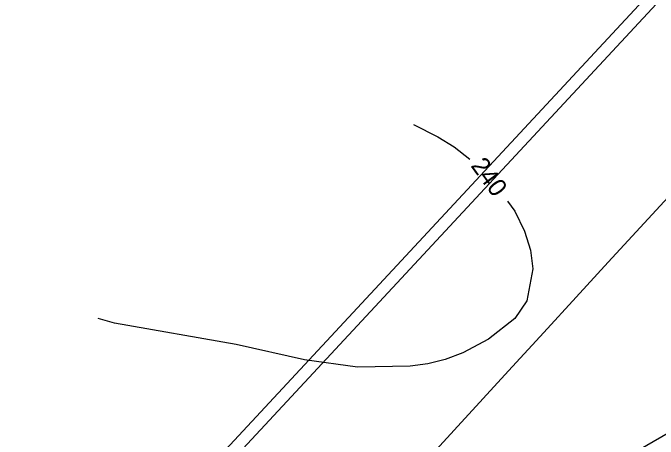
# Model space of a CAD drawing. Extents: x -555887 to -552101, y -1100251 to -1096546.
# Drawn here: x -555592.8 to -555325, y -1098138.5 to -1097961.6 of the extents above; entities that cross this region are included whole.
import ezdxf

# ---------------------------------------------------------------- set-up
doc = ezdxf.new("R2010")
doc.units = 0
for name, color, linetype in [('PARCELY_ZP', 7, 'Continuous'), ('ram_VC1', 7, 'Continuous'), ('vrstevnice', 7, 'Continuous'), ('zájem', 7, 'Continuous')]:
    doc.layers.add(name, color=color, linetype=linetype)

msp = doc.modelspace()

# ---------------------------------------------------------------- linework, layer by layer
at = {"layer": 'PARCELY_ZP'}
msp.add_lwpolyline([(-555445.24, -1098173.52), (-555417.39, -1098184.68), (-555381.15, -1098170.85), (-555299.54, -1098123.63), (-555285.35, -1098108), (-555279.05, -1098060.74), (-555272.16, -1098043.88), (-555262.31, -1098025.87), (-555247.78, -1098012.9), (-555216.95, -1097989.98), (-555203.13, -1097974.15), (-555172.13, -1097938.12), (-555158.62, -1097923.19), (-555154.87, -1097919.14), (-555147.19, -1097910.97), (-555141.65, -1097905.03), (-555123.73, -1097886.21), (-555084.65, -1097845.81), (-554996.25, -1097738.07)], dxfattribs=at)
at = {"layer": 'ram_VC1'}
for points in [[(-554540.88, -1097849.11), (-554911.62, -1097504.63), (-555880.62, -1098547.51), (-555509.88, -1098891.98)], [(-554547.95, -1097849.37), (-554911.36, -1097511.7), (-555873.55, -1098547.25), (-555510.14, -1098884.91)]]:
    msp.add_lwpolyline(points, close=True, dxfattribs=at)
for points in [[(-554540.88, -1097849.11), (-554911.62, -1097504.63), (-555880.62, -1098547.51), (-555509.88, -1098891.98), (-554540.88, -1097849.11)], [(-555510.14, -1098884.91), (-555873.55, -1098547.25), (-554911.36, -1097511.7), (-554547.95, -1097849.37), (-555510.14, -1098884.91)]]:
    msp.add_lwpolyline(points, dxfattribs=at)
at = {"layer": 'vrstevnice'}
for p, q in [((-555426.55, -1098007.93), (-555416.44, -1098012.99)), ((-555416.44, -1098012.99), (-555409.7, -1098017.2)), ((-555409.7, -1098017.2), (-555403.24, -1098022.26)), ((-555384.56, -1098043.88), (-555380.49, -1098052.17)), ((-555380.49, -1098052.17), (-555377.97, -1098060.03)), ((-555377.97, -1098060.03), (-555376.98, -1098067.89)), ((-555376.98, -1098067.89), (-555379.57, -1098081.08)), ((-555379.57, -1098081.08), (-555384.56, -1098088.53)), ((-555550.68, -1098090.36), (-555557.42, -1098088.53)), ((-555384.56, -1098088.53), (-555395.38, -1098097.1)), ((-555500.13, -1098099.21), (-555550.68, -1098090.36)), ((-555395.38, -1098097.1), (-555406.05, -1098102.72)), ((-555471.76, -1098105.66), (-555500.13, -1098099.21)), ((-555406.05, -1098102.72), (-555413.35, -1098105.52)), ((-555449.86, -1098108.61), (-555471.76, -1098105.66)), ((-555413.35, -1098105.52), (-555420.65, -1098107.35)), ((-555427.95, -1098108.19), (-555449.86, -1098108.61)), ((-555420.65, -1098107.35), (-555427.95, -1098108.19))]:
    msp.add_line(p, q, dxfattribs=at)
for points in [[(-555426.55, -1098007.93), (-555416.44, -1098012.99), (-555409.7, -1098017.2), (-555403.24, -1098022.26)], [(-555387.51, -1098039.74), (-555384.56, -1098043.88), (-555380.49, -1098052.17), (-555377.97, -1098060.03), (-555376.98, -1098067.89), (-555379.57, -1098081.08), (-555384.56, -1098088.53), (-555395.38, -1098097.1), (-555406.05, -1098102.72), (-555413.35, -1098105.52), (-555420.65, -1098107.35), (-555427.95, -1098108.19), (-555449.86, -1098108.61), (-555471.76, -1098105.66), (-555500.13, -1098099.21), (-555550.68, -1098090.36), (-555557.42, -1098088.53)]]:
    msp.add_lwpolyline(points, dxfattribs=at)
at = {"layer": 'zájem'}
for points in [[(-555238.64, -1097948.52), (-555252.57, -1097963.73), (-555279.76, -1097993.33), (-555293.44, -1098008.21), (-555307.4, -1098023.39), (-555319.27, -1098036.32), (-555345.7, -1098065.12), (-555359.04, -1098079.61), (-555372.52, -1098094.26), (-555387.16, -1098110.21), (-555420.24, -1098146.3), (-555426.79, -1098153.42), (-555433.69, -1098160.92), (-555440.91, -1098168.86), (-555445.23, -1098173.52), (-555448.48, -1098177.05), (-555451.73, -1098180.59), (-555493.09, -1098225.57), (-555626.26, -1098371.34)], [(-555626.26, -1098371.34), (-555493.09, -1098225.57), (-555451.73, -1098180.59), (-555448.48, -1098177.05), (-555445.23, -1098173.52), (-555440.91, -1098168.86), (-555433.69, -1098160.92), (-555426.79, -1098153.42), (-555420.24, -1098146.3), (-555387.16, -1098110.21), (-555372.52, -1098094.26), (-555359.04, -1098079.61), (-555345.7, -1098065.12), (-555319.27, -1098036.32), (-555307.4, -1098023.39), (-555293.44, -1098008.21), (-555279.76, -1097993.33), (-555252.57, -1097963.73), (-555238.64, -1097948.52)]]:
    msp.add_lwpolyline(points, dxfattribs=at)

# ---------------------------------------------------------------- texts
at = {"layer": 'vrstevnice'}
msp.add_text('240', height=7.5, rotation=306.1886, dxfattribs=at).set_placement((-555403.04, -1098025.06))

doc.saveas('drawing.dxf')
